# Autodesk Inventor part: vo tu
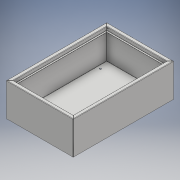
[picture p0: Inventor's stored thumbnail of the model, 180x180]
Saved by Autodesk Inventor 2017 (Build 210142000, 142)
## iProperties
Created: 2022-04
Part Number: vo tu
Material: Generic
Document SubType Name: Sheet Metal
Designer: phat
Density: 1 g/cm^3
Sheet Metal Rule: Default_mm
Appearance: Default
Author: phat
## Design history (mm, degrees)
node "Face1"
  sketch "Sketch1"
    geometry: L1 (-200, 300)-(200, 300); L2 (200, 300)-(200, -300); L3 (200, -300)-(-200, -300); L4 (-200, -300)-(-200, 300); L5 (-200, 300)-(200, -300); L6 (200, 300)-(-200, -300); 1 further point
    constraints: 12 end point, 2 midpoint, 2 parallel, 1 horizontal, 1 perpendicular
    dimensions: "d0" = 400 distance of L2.end L3.end; "d1" = 600 distance of L1.end L2.end
sketch "Sketch2" dims "d11" = 10
  geometry: L1 (-200, 300)-(200, 300) reference; L2 (-200, -300)-(-200, 300) reference; L3 (200, 300)-(200, -300) reference; L4 (200, 300)-(200, -300) reference; L5 (-200, 300)-(200, 300) reference; L6 (-200, -300)-(-200, 300) reference; L7 (200, -300)-(-200, -300) reference; C1 r 5 at (-178, 240); C2 r 5 at (178, 240); C3 r 5 at (178, -240); C4 r 5 at (-178, -240); 5 further points
  constraints: 4 centre point, 3 coincident, 2 horizontal, 1 vertical, 5 other
  dimensions: "d3" = 60 distance from line of L1 point (-178, 240); "d4" = 22 distance from line of L2 point (-178, 240); "d5" = 10 diameter of C1; "d8" = 356 distance of C1.centre C2.centre; "d15" = 480 distance of C2.centre point (178, -240); "d18" = 356 distance of C2.centre point (-178, 240); "d21" = 10 diameter of C3; "d22" = 10 diameter of C4
hole "Hole1" sketch "Sketch2" at (-178, 240), (178, 240), (178, -240), (-178, -240) diameter "d23" = 10; stored, may be unused: countersink angle "d27" = 90 deg, drill point angle "d29" = 118 deg; dims "d24" = 6, "d25" = 4, "d26" = 2, "d28" = 1.2 (= Thickness)
node "Flange1"
node "Flange2"
node "Flange3"
node "Flange4"
sketch "Sketch7"
  geometry: L1 (0, 0)-(0, 16.2) reference; L2 (0, 0)-(356.303, 0) reference; C1 r 2.5 at (5, 5); 2 further points
  constraints: 1 centre point, 1 coincident
  dimensions: "d70" = 5 distance from line of point (5, 5) L1; "d71" = 5 distance from line of L2 point (5, 5); "d72" = 5 diameter of C1
cut "Cut1" sketch "Sketch7" dims "d73" = 1.2 (= Thickness), "d74" = 0
workplane "Work Plane1"
mirror "Mirror1"
body "Solid1"
face "Plate1" dims "Thickness" = 1.2 (derived)
node "Projected Loop1"
sketch "Sketch3"
  geometry: L1 through (-200, 0) direction (1, 0); L2 through (0, 100) direction (0, 1); L3 (0, 200)-(-400, 200); L4 (-400, 200)-(-400, 0)
  constraints: 6 end point, 1 horizontal, 1 perpendicular, 1 vertical
face "Plate2" dims "d30" = 1.2 (= BendReliefWidth), "d31" = 0.6 (= BendReliefDepth), "d32" = 2.4 (= MinimumRemnant), "d33" = 1.2 (= BendRadius), "d34" = 200, "d35" = 90 deg, "d36" = 1.2 (= BendRadius), "d37" = 4.8 (= CornerReliefSize), "d38" = 1.2 (= GapSize), "d39" = 1.2 (= JacobiRadiusSize), "SeamGap" = 0.01, "Thickness" = 1.2 (derived)
bend "Bend1" dims "d30" = 1.2 (= BendReliefWidth), "d31" = 0.6 (= BendReliefDepth), "d32" = 2.4 (= MinimumRemnant), "d33" = 1.2 (= BendRadius), "d34" = 200, "d35" = 90 deg, "d36" = 1.2 (= BendRadius), "SeamGap" = 0.01, "Thickness" = 1.2 (derived)
feature "Corner1" dims "d34" = 200, "d35" = 90 deg, "d37" = 4.8 (= CornerReliefSize), "d38" = 1.2 (= GapSize), "d39" = 1.2 (= JacobiRadiusSize)
sketch "Sketch4"
  geometry: L1 through (0, 297.951) direction (3.58e-16, -1); L2 through (10.5, 0) direction (1, -3.03e-32); L3 (21, 0)-(21, 595.903); L4 (21, 595.903)-(0, 595.903)
  constraints: 6 end point, 1 horizontal, 1 perpendicular, 1 vertical
face "Plate3" dims "d40" = 1.2 (= BendReliefWidth), "d41" = 0.6 (= BendReliefDepth), "d42" = 2.4 (= MinimumRemnant), "d43" = 1.2 (= BendRadius), "d44" = 21, "d45" = 90 deg, "d46" = 1.2 (= BendRadius), "d47" = 4.8 (= CornerReliefSize), "d48" = 1.2 (= GapSize), "d49" = 1.2 (= JacobiRadiusSize), "SeamGap" = 0.01, "Thickness" = 1.2 (derived)
bend "Bend2" dims "d40" = 1.2 (= BendReliefWidth), "d41" = 0.6 (= BendReliefDepth), "d42" = 2.4 (= MinimumRemnant), "d43" = 1.2 (= BendRadius), "d44" = 21, "d45" = 90 deg, "d46" = 1.2 (= BendRadius), "SeamGap" = 0.01, "Thickness" = 1.2 (derived)
feature "Corner2" dims "d44" = 21, "d45" = 90 deg, "d47" = 4.8 (= CornerReliefSize), "d48" = 1.2 (= GapSize), "d49" = 1.2 (= JacobiRadiusSize)
sketch "Sketch5"
  geometry: L1 through (178.151, 0) direction (-1, -1.43e-31); L2 through (0, -10.5) direction (-3.23e-30, -1); L3 (0, -21)-(356.303, -21); L4 (356.303, -21)-(356.303, 0)
  constraints: 6 end point, 1 horizontal, 1 perpendicular, 1 vertical
face "Plate4" dims "d50" = 1.2 (= BendReliefWidth), "d51" = 0.6 (= BendReliefDepth), "d52" = 2.4 (= MinimumRemnant), "d53" = 1.2 (= BendRadius), "d54" = 21, "d55" = 90 deg, "d56" = 1.2 (= BendRadius), "d57" = 4.8 (= CornerReliefSize), "d58" = 1.2 (= GapSize), "d59" = 1.2 (= JacobiRadiusSize), "SeamGap" = 0.01, "Thickness" = 1.2 (derived)
bend "Bend3" dims "d50" = 1.2 (= BendReliefWidth), "d51" = 0.6 (= BendReliefDepth), "d52" = 2.4 (= MinimumRemnant), "d53" = 1.2 (= BendRadius), "d54" = 21, "d55" = 90 deg, "d56" = 1.2 (= BendRadius), "SeamGap" = 0.01, "Thickness" = 1.2 (derived)
feature "Corner3" dims "d54" = 21, "d55" = 90 deg, "d57" = 4.8 (= CornerReliefSize), "d58" = 1.2 (= GapSize), "d59" = 1.2 (= JacobiRadiusSize)
sketch "Sketch6"
  geometry: L1 through (0, -278.151) direction (7.02e-16, 1); L2 through (-5.5, 0) direction (-1, 4.6e-32); L3 (-11, 0)-(-11, -556.303); L4 (-11, -556.303)-(0, -556.303)
  constraints: 6 end point, 1 horizontal, 1 perpendicular, 1 vertical
face "Plate5" dims "d60" = 1.2 (= BendReliefWidth), "d61" = 0.6 (= BendReliefDepth), "d62" = 2.4 (= MinimumRemnant), "d63" = 1.2 (= BendRadius), "d64" = 11, "d65" = 90 deg, "d66" = 1.2 (= BendRadius), "d67" = 4.8 (= CornerReliefSize), "d68" = 1.2 (= GapSize), "d69" = 1.2 (= JacobiRadiusSize), "SeamGap" = 0.01, "Thickness" = 1.2 (derived)
bend "Bend4" dims "d60" = 1.2 (= BendReliefWidth), "d61" = 0.6 (= BendReliefDepth), "d62" = 2.4 (= MinimumRemnant), "d63" = 1.2 (= BendRadius), "d64" = 11, "d65" = 90 deg, "d66" = 1.2 (= BendRadius), "SeamGap" = 0.01, "Thickness" = 1.2 (derived)
feature "Corner4" dims "d64" = 11, "d65" = 90 deg, "d67" = 4.8 (= CornerReliefSize), "d68" = 1.2 (= GapSize), "d69" = 1.2 (= JacobiRadiusSize)
other parameters: "BendRadius" = 1.2 (= Thickness), "BendReliefWidth" = 1.2 (= Thickness), "BendReliefDepth" = 0.6 (= 0.5 x Thickness), "CornerReliefSize" = 4.8 (= 4 x Thickness), "MinimumRemnant" = 2.4 (= 2 x Thickness), "TransitionRadius" = 1.2 (= BendRadius), "JacobiRadiusSize" = 1.2 (= BendRadius), "GapSize" = 1.2 (= Thickness), "d2" = 1.2 (= BendRadius)
